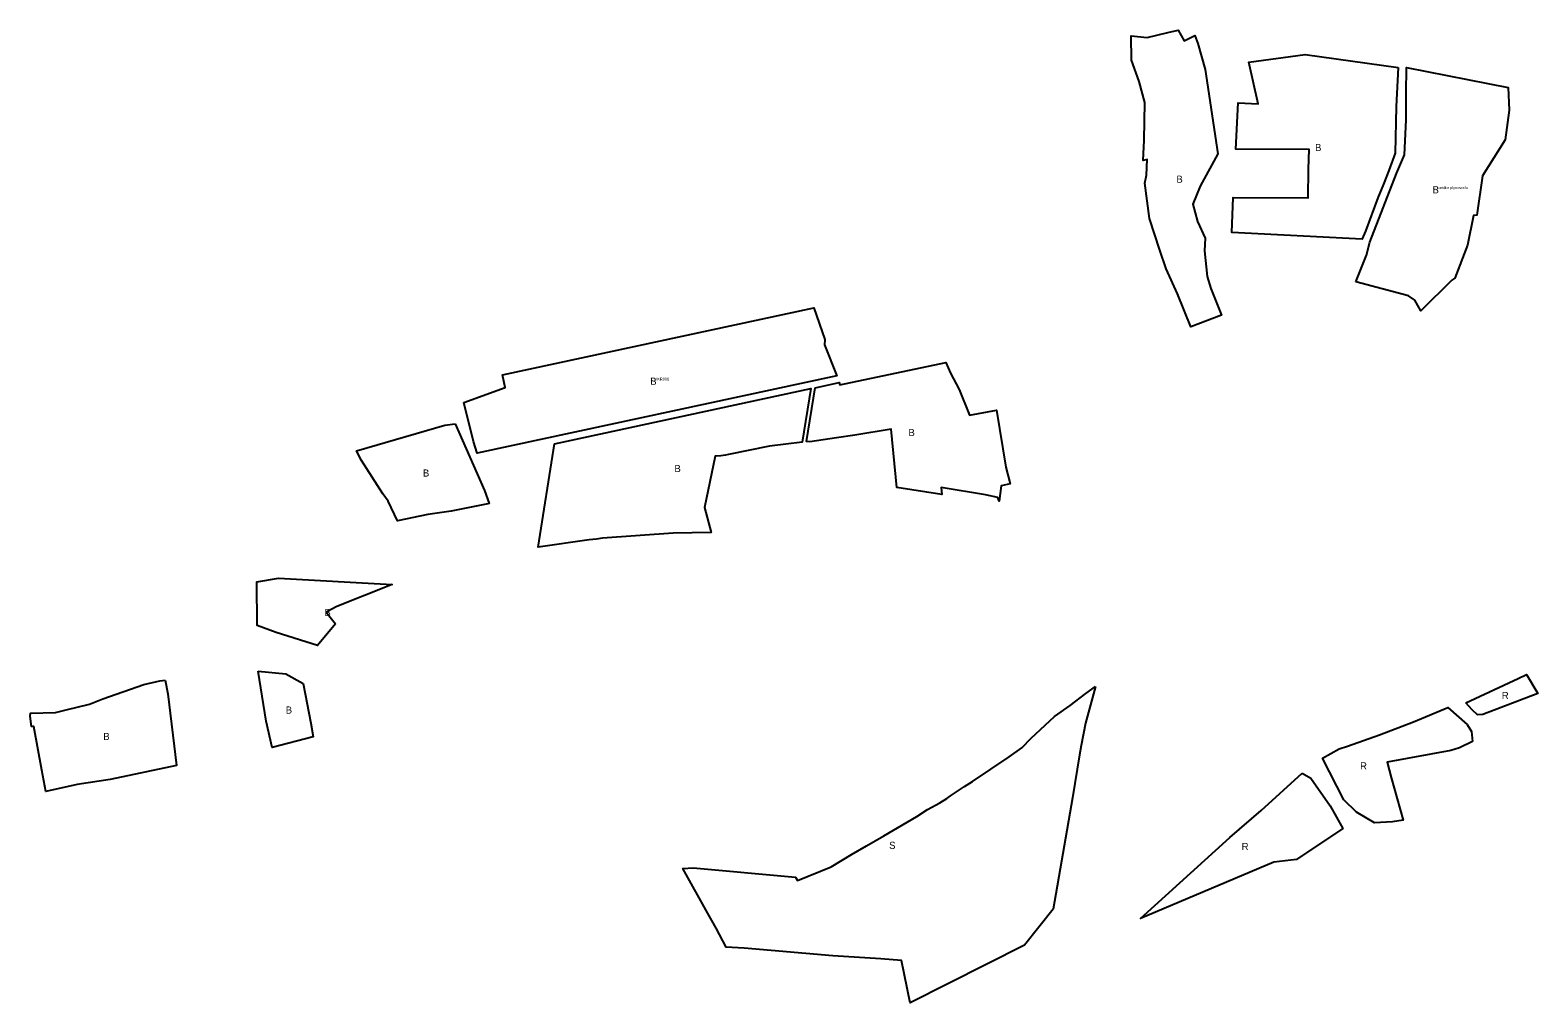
# Model space of a CAD drawing. Extents: x -476493 to -466317, y -1156890 to -1150260.
# Drawn here: x -473918 to -472858, y -1154114 to -1153430 of the extents above; entities that cross this region are included whole.
import ezdxf

# ---------------------------------------------------------------- set-up
doc = ezdxf.new("R2010")
doc.units = 0
for name, color, linetype in [('Vrstva 1', 7, 'Continuous'), ('Vrstva 6', 7, 'Continuous'), ('Vrstva 7', 7, 'Continuous')]:
    doc.layers.add(name, color=color, linetype=linetype)

msp = doc.modelspace()

# ---------------------------------------------------------------- linework, layer by layer
at = {"layer": 'Vrstva 1'}
for points in [[(-473134.73, -1153507.71), (-473134.17, -1153481.19), (-473138.13, -1153466.34), (-473143.58, -1153451.26), (-473143.8, -1153434.37), (-473132.6, -1153435.36), (-473118.12, -1153432.02), (-473110.69, -1153430.29), (-473106.61, -1153437.84), (-473099.06, -1153434.12), (-473096.95, -1153439.57), (-473091.88, -1153457.89), (-473082.84, -1153517.18), (-473095.22, -1153539.96), (-473100.54, -1153552.59), (-473097.32, -1153564.72), (-473091.75, -1153576.48), (-473092.25, -1153585.27), (-473090.52, -1153603.34), (-473087.79, -1153611.88), (-473080.27, -1153630.48), (-473101.97, -1153638.75), (-473111.16, -1153615.52), (-473119.32, -1153598.06), (-473123.63, -1153585.02), (-473130.99, -1153562.69), (-473134.28, -1153537.75), (-473133.15, -1153532.09), (-473132.58, -1153521.2), (-473135.41, -1153522)], [(-472956.059, -1153456.566), (-472957.549, -1153483.942), (-472958.286, -1153516.729), (-472962.556, -1153528.927), (-472966.454, -1153538.578), (-472970.352, -1153548.228), (-472979.018, -1153571.497), (-472981.375, -1153576.954), (-472981.476, -1153577.257), (-473073, -1153572.58), (-473072.01, -1153547.82), (-473019.28, -1153548.07), (-473019.03, -1153528.02), (-473018.78, -1153514.15), (-473070.28, -1153513.9), (-473068.54, -1153481.47), (-473054.49, -1153482), (-473061.175, -1153452.66), (-473021.443, -1153447.289)], [(-472985.807, -1153607.255), (-472978.408, -1153588.469), (-472975.936, -1153579.292), (-472957.297, -1153531.024), (-472951.72, -1153517.976), (-472950.52, -1153493.257), (-472950.37, -1153474.887), (-472950.22, -1153456.516), (-472878.825, -1153470.55), (-472878, -1153486.52), (-472880.79, -1153507.37), (-472896.88, -1153532.75), (-472900.72, -1153560.35), (-472903.2, -1153560.6), (-472907.28, -1153581.4), (-472916.32, -1153604.55), (-472918.42, -1153606.03), (-472940.08, -1153627.45), (-472944.29, -1153620.02), (-472948.87, -1153617.05)], [(-473613.21, -1153691.89), (-473584.08, -1153681.51), (-473586.047, -1153672.484), (-473366.955, -1153625.498), (-473359.38, -1153647.78), (-473359.5, -1153651.49), (-473350.918, -1153673.192), (-473603.69, -1153727.56), (-473606.25, -1153719.32)], [(-473366.021, -1153681.555), (-473349.213, -1153677.986), (-473348.73, -1153679.47), (-473274.15, -1153663.87), (-473270.93, -1153671.42), (-473264.87, -1153682.81), (-473257.57, -1153700.88), (-473238.59, -1153697.35), (-473232.07, -1153737.4), (-473228.85, -1153749.04), (-473235.16, -1153750.52), (-473236.65, -1153761.29), (-473237.64, -1153758.69), (-473246.18, -1153756.96), (-473277.43, -1153751.76), (-473276.88, -1153756.59), (-473287.52, -1153755.1), (-473308.69, -1153751.64), (-473312.59, -1153710.66), (-473338.228, -1153714.995), (-473350.995, -1153716.85), (-473369.72, -1153719.57), (-473372.1, -1153719.48)], [(-473549.468, -1153721.012), (-473369.139, -1153682.226), (-473375.29, -1153719.76), (-473398.25, -1153722.67), (-473427.09, -1153728.62), (-473429.13, -1153729.04), (-473432.5, -1153729.39), (-473436.44, -1153729.79), (-473443.86, -1153765.69), (-473439.13, -1153783.26), (-473465.85, -1153783.69), (-473515.59, -1153787.24), (-473519.85, -1153787.95), (-473524.97, -1153788.38), (-473560.941, -1153793.583)], [(-473619.33, -1153706.95), (-473598.58, -1153753.85), (-473595.289, -1153762.883), (-473596.27, -1153763.3), (-473621.99, -1153768.34), (-473638.47, -1153770.62), (-473659.83, -1153775.13), (-473666.36, -1153761.34), (-473670.02, -1153756.16), (-473685.01, -1153732.78), (-473688.508, -1153725.886), (-473626.57, -1153707.95)], [(-473703.42, -1153847.53), (-473716.03, -1153862.68), (-473745.02, -1153853.7), (-473758.41, -1153848.78), (-473758.79, -1153818.1), (-473743.53, -1153815.38), (-473663.61, -1153819.91), (-473702.42, -1153835.24), (-473709.88, -1153839.22)], [(-473757.74, -1153880.91), (-473738.41, -1153882.6), (-473726.2, -1153889.39), (-473720.85, -1153917.27), (-473719.01, -1153926.86), (-473748.02, -1153934.34), (-473752.14, -1153916)], [(-473823.18, -1153887.01), (-473821.3, -1153896.74), (-473815.19, -1153947.04), (-473861.94, -1153956.99), (-473885.1, -1153960.54), (-473907.02, -1153965.31), (-473909.98, -1153950.3), (-473915.53, -1153919.62), (-473917.08, -1153919.62), (-473918.12, -1153912.52), (-473917.95, -1153910.24), (-473900.32, -1153909.9), (-473892.69, -1153908.03), (-473876.41, -1153903.97), (-473867.09, -1153900.24), (-473838.27, -1153890.06), (-473826.91, -1153887.69)]]:
    msp.add_lwpolyline(points, close=True, dxfattribs=at)
at = {"layer": 'Vrstva 6'}
for points in [[(-472908.53, -1153902.95), (-472871.72, -1153886.01), (-472865.9, -1153883.16), (-472857.86, -1153896.4), (-472896.48, -1153911.26), (-472900.39, -1153911.6), (-472904.12, -1153908.03)], [(-472903.91, -1153930.32), (-472913.07, -1153934.65), (-472919.01, -1153936.51), (-472963.848, -1153944.85), (-472960.91, -1153955.51), (-472952.62, -1153985.59), (-472960.17, -1153986.71), (-472972.67, -1153987.45), (-472985.42, -1153979.9), (-472994.21, -1153971.23), (-473009.19, -1153942.02), (-472997.55, -1153935.46), (-472991.61, -1153933.6), (-472969.2, -1153925.43), (-472945.38, -1153916.33), (-472921.24, -1153906.34), (-472907.68, -1153918.38), (-472904.63, -1153923.12)], [(-473023.61, -1153952.52), (-473017.47, -1153956.03), (-473003.96, -1153975.49), (-472995.02, -1153991.27), (-473027.64, -1154013.2), (-473043.6, -1154015.12), (-473137.24, -1154054.58), (-473074.46, -1153997.59), (-473052.54, -1153978.65)]]:
    msp.add_lwpolyline(points, close=True, dxfattribs=at)
at = {"layer": 'Vrstva 7'}
msp.add_lwpolyline([(-473168.94, -1153891.51), (-473176.06, -1153917.27), (-473178.94, -1153933.04), (-473180.12, -1153939.65), (-473185.04, -1153969.83), (-473198.77, -1154047.99), (-473218.95, -1154073.42), (-473299.267, -1154113.893), (-473305.355, -1154084.111), (-473319.8, -1154083.06), (-473353.65, -1154080.8), (-473415.99, -1154075.59), (-473428.68, -1154074.74), (-473435.73, -1154061.41), (-473441.795, -1154050.55), (-473459.14, -1154019.52), (-473451.81, -1154019.1), (-473380.02, -1154025.59), (-473378.47, -1154027.99), (-473354.78, -1154018.25), (-473340.53, -1154009.65), (-473329.95, -1154003.44), (-473317.68, -1153996.53), (-473294.475, -1153982.825), (-473287.08, -1153978.06), (-473278.33, -1153973.4), (-473273.5, -1153970.21), (-473270.86, -1153968.47), (-473261.13, -1153961.84), (-473255.48, -1153958.31), (-473229.67, -1153940.96), (-473220.79, -1153934.62), (-473214.16, -1153927.99), (-473197.8, -1153912.62), (-473186.8, -1153905), (-473175.8, -1153896.54)], close=True, dxfattribs=at)

# ---------------------------------------------------------------- texts
at = {"layer": 'Vrstva 1'}
for s, height, p in [('B', 5, (-473014.53, -1153515.273)), ('B', 5, (-473112.035, -1153537.52)), ('1: koridor plynovodu', 2, (-472931.904, -1153541.983)), ('B', 5, (-472931.904, -1153544.983)), ('1: VKR006', 2, (-473482.064, -1153676.529)), ('B', 5, (-473482.064, -1153679.529)), ('B', 5, (-473300.475, -1153715.58)), ('B', 5, (-473641.898, -1153744.04)), ('B', 5, (-473465.04, -1153740.904)), ('B', 5, (-473711.2, -1153842.03)), ('R', 5, (-472883.195, -1153900.38)), ('B', 5, (-473738.375, -1153910.625)), ('B', 5, (-473866.655, -1153929.16)), ('R', 5, (-472982.87, -1153949.895)), ('S', 5, (-473314.04, -1154005.702)), ('R', 5, (-473066.13, -1154006.55))]:
    msp.add_text(s, height=height, dxfattribs=at).set_placement(p)

doc.saveas('drawing.dxf')
